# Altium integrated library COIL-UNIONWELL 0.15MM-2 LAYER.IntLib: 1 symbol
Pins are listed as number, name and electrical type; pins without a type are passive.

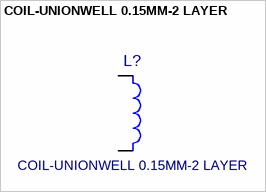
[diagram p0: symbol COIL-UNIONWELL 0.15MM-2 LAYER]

## COIL-UNIONWELL 0.15MM-2 LAYER
designator L?
Int_Part_Number: NONE; Manufacturer: AZOTEQ; 3D_Part: No; Checked_By: Jason Reinecke; Tolerance: na; Int_Note: Created for Elijah Chigwada; Generated_By: JR; Pin_Count: 2; Type: SMT; Dept.: ProxSense
footprint COIL-COIL-UNIONWELL 0.15MM-2 LAYER-LEFT BOTTOM (COIL 2 Layer, 2-Lead, mmxmm, IPC Medium Density)
footprint COIL-COIL-UNIONWELL 0.15MM-2 LAYER-LEFT TOP (COIL 2 Layer, 2-Lead, mmxmm, IPC Medium Density)
footprint COIL-COIL-UNIONWELL 0.15MM-2 LAYER-RIGHT BOT (COIL 2 Layer, 2-Lead, mmxmm, IPC Medium Density)
footprint COIL-COIL-UNIONWELL 0.15MM-2 LAYER-RIGHT TOP (COIL 2 Layer, 2-Lead, mmxmm, IPC Medium Density)
pins: 1, 2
